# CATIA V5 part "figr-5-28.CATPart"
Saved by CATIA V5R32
Part number: Part1
Bounding box of the stored display mesh (mm): x -100 to 100, y -100 to 100, z 0 to 57
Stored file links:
  D:\PROJECTS\Project 2022\CATIA V5 6R 2022\Resources\Part Files\c05_catia_v5_6r2022_prt\figr-5-28.CATPart
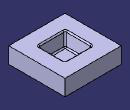
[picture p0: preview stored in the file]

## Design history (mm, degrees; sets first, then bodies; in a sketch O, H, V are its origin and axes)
Body1 (main body)
  Sketch1 on xy-plane, origin (0, 0, 0), H (1, 0, 0), V (0, 1, 0)
    line L1 (-100, 100) -> (100, 100)
    line L2 (100, 100) -> (100, -100)
    line L3 (100, -100) -> (-100, -100)
    line L4 (-100, -100) -> (-100, 100)
    axis line L5 (100, -100) -> (-100, 100)
    length L3 = 200
    length L2 = 200
    horizontal: L1 H, L3 H
    vertical: L2 V, L4 V
    midpoint: L5 O
  Pad1: profile Sketch1, direction (0, 0, 1), length 57
  Sketch2 on face of Pad1, origin (0, 0, 57), H (1, 0, 0), V (0, 1, 0)
    line L1 (-48.5141, 47.7936) -> (48.5141, 47.7936)
    line L2 (48.5141, 47.7936) -> (48.5141, -47.7936)
    line L3 (48.5141, -47.7936) -> (-48.5141, -47.7936)
    line L4 (-48.5141, -47.7936) -> (-48.5141, 47.7936)
    axis line L5 (48.5141, -47.7936) -> (-48.5141, 47.7936)
    horizontal: L1 H, L3 H
    vertical: L2 V, L4 V
    midpoint: O L5
  Pocket1: profile Sketch2, direction (0, 0, -1), length 42, opposite side up to face of Pad1
  Draft1: Angle 15, Neutral face of Pad1, PullDir face of Pocket1, SupportToDraft (face of Pocket1; face of Pocket1; face of Pocket1; face of Pocket1)
  Fillet1: radius 5, on edge [face of Pocket1 | face of Pocket1] (x4)
  Fillet2: radius 5, on edge [face of Pocket1 | face of Pocket1] (x4)
  Fillet3: radius 5, on edge [face of Pocket1 | face of Pad1]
